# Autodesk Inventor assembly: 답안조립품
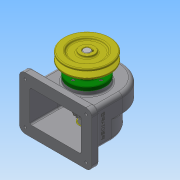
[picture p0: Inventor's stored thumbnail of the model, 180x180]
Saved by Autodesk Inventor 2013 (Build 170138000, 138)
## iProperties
Created: 2017-11
Part Number: 답안조립품
Document SubType Name: Assembly
Designer: Administrator
Author: Administrator
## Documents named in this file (14)
- C:\Users\Administrator\Desktop\471108V1017\답안조립품.iam
- C:\Users\Administrator\Desktop\471108V1017\본체.ipt
- C:\Users\Administrator\Desktop\471108V1017\V-벨트풀리.ipt
- C:\Users\Administrator\Desktop\471108V1017\뒤커버.ipt
- C:\Users\Administrator\Desktop\471108V1017\멈춤나사 - M4 x 10.ipt
- 멈춤나사 - M4 x 10.ipt
- C:\Users\Administrator\Desktop\471108V1017\베어링 6002.ipt
- C:\Users\Administrator\Desktop\471108V1017\볼트 M3 x 8.ipt
- C:\Users\Administrator\Desktop\471108V1017\스퍼기어.ipt
- C:\Users\Administrator\Desktop\471108V1017\앞커버.ipt
- C:\Users\Administrator\Desktop\471108V1017\오일 실 15 30 7.ipt
- C:\Users\Administrator\Desktop\471108V1017\축.ipt
- C:\Users\Administrator\Desktop\471108V1017\키 - 5 x 5 x 18.ipt
- C:\Users\Administrator\Desktop\471108V1017\키 - 6 x 6 x 22.ipt
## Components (1 placed, 1 different names)
1. V-벨트풀리:1
